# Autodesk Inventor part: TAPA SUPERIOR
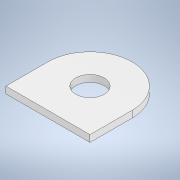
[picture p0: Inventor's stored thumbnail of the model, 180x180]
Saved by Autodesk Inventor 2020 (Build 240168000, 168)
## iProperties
Created: 2022-09
Part Number: TAPA SUPERIOR
Material: Tuberías de PVC
Document SubType Name: Modeling
Designer: SEBAS
Density: 1.4 g/cm^3
Appearance: Suave - Blanco
Author: SEBAS
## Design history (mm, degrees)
sketch "Boceto1"
  geometry: L1 (31, 0)-(31, 31); L2 (-31, 31)-(-31, 0); L3 (31, 31)-(-31, 31); C1 r 10.5 at (0, 0); A1 r 31 centre (0, 0) between (-31, 0) and (31, 0); 2 further points
  constraints: 6 end point, 3 vertical alignment, 2 centre point, 2 coincident, 2 point on circle, 1 horizontal alignment, 1 midpoint
  dimensions: "d1" = 31 distance of L1.start L1.end; "d2" = 62 distance between parallel lines of L2 L1; "d5" = 31 radius of A1; "d6" = 21 diameter of C1
extrude "Extrusión2" new body sketch "Boceto1" distance "d7" = 5; taper "d8" = 0 deg
node "Sólido2"
